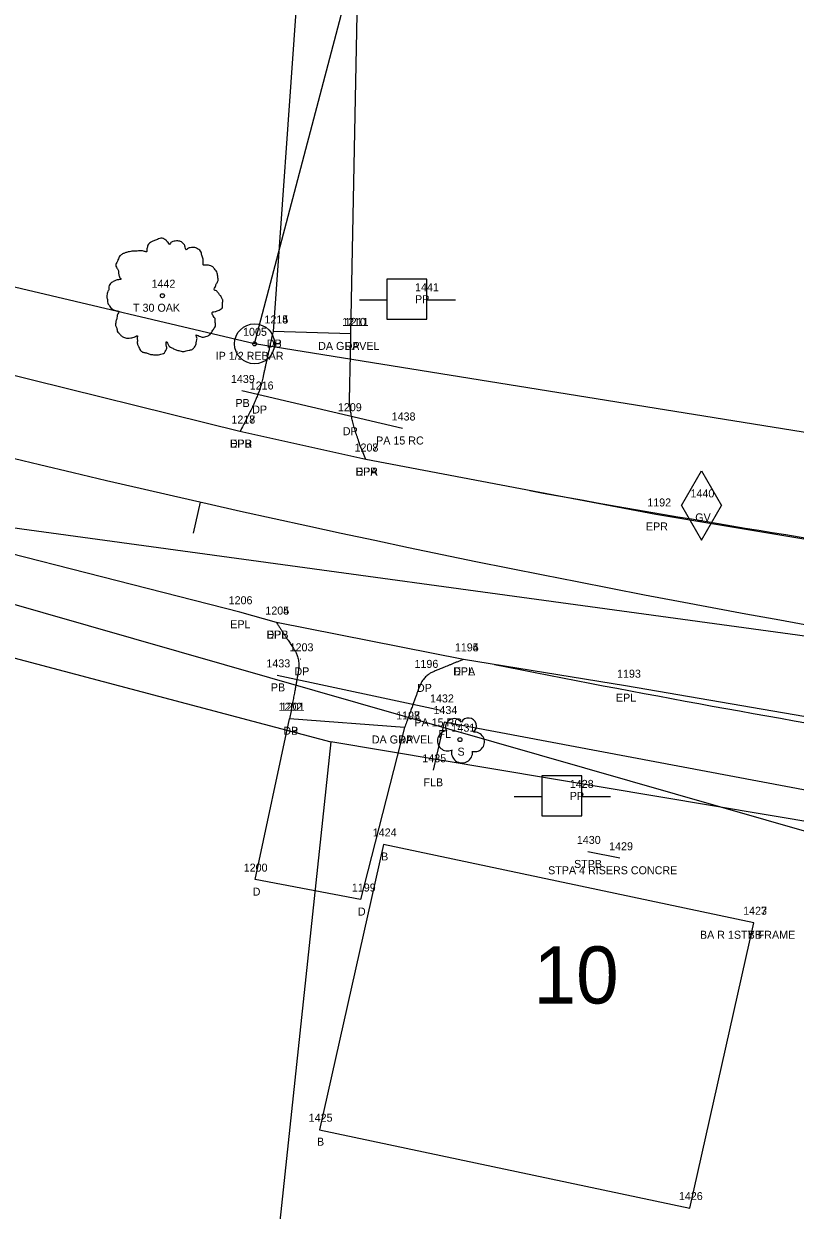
# Model space of a CAD drawing. Extents: x 1812113 to 1819860, y 1177395 to 1181185.
# Drawn here: x 1813371.7 to 1813468, y 1178709.1 to 1178857.4 of the extents above; entities that cross this region are included whole.
import ezdxf

# ---------------------------------------------------------------- set-up
doc = ezdxf.new("R2010")
doc.units = 0
for name, color, linetype in [('RD_EX_Bldg', 7, 'Continuous'), ('RD_EX_Bldg_txCode', 7, 'Continuous'), ('RD_EX_Conc', 7, 'Continuous'), ('RD_EX_Conc_txCode', 7, 'Continuous'), ('RD_EX_DR_Pipe', 7, 'Continuous'), ('RD_EX_DR_Pipe_txCode', 7, 'Continuous'), ('RD_EX_Driveway', 7, 'Continuous'), ('RD_EX_Driveway_txCode', 7, 'Continuous'), ('RD_EX_DV_Prop', 7, 'Continuous'), ('RD_EX_DV_Prop_txCode', 7, 'Continuous'), ('RD_EX_DV_PropPin', 7, 'Continuous'), ('RD_EX_DV_TX_Prop', 7, 'Continuous'), ('RD_EX_Fence_Other', 7, 'Continuous'), ('RD_EX_Fence_Other_txCode', 7, 'Continuous'), ('RD_EX_Road', 7, 'Continuous'), ('RD_EX_Road_txCode', 7, 'Continuous'), ('RD_EX_RW', 7, 'Continuous'), ('RD_EX_UT', 7, 'Continuous'), ('RD_EX_UT_txCode', 7, 'Continuous'), ('RD_EX_VEG', 7, 'Continuous'), ('RD_EX_VEG_txCode', 7, 'Continuous'), ('RD_HC_CL', 7, 'Continuous'), ('RD_HC_Data_Tic', 7, 'Continuous'), ('RD_PD_ALT1_TrvlWay', 7, 'Continuous'), ('RD_PD_PatLn1', 7, 'Continuous'), ('RD_SMD_Locator', 7, 'Continuous')]:
    doc.layers.add(name, color=color, linetype=linetype)

msp = doc.modelspace()

# ---------------------------------------------------------------- linework, layer by layer
at = {"layer": 'RD_EX_Bldg'}
msp.add_lwpolyline([(1813462.81, 1178745.04), (1813416.58, 1178754.82), (1813408.58, 1178719.18), (1813454.82, 1178709.39), (1813462.81, 1178745.04)], dxfattribs=at)
at = {"layer": 'RD_EX_Conc'}
msp.add_line((1813446.08, 1178753.1), (1813442.1, 1178753.89), dxfattribs=at)
at = {"layer": 'RD_EX_DR_Pipe'}
for p, q in [((1813418.94, 1178806.8), (1813398.87, 1178811.49)), ((1813423.73, 1178771.57), (1813403.29, 1178775.95))]:
    msp.add_line(p, q, dxfattribs=at)
at = {"layer": 'RD_EX_Driveway'}
for p, q in [((1813405.99, 1178863.99), (1813402.78, 1178818.92)), ((1813412.51, 1178818.62), (1813413.38, 1178863.09)), ((1813412.51, 1178818.62), (1813402.78, 1178818.92)), ((1813419.21, 1178769.44), (1813404.84, 1178770.53))]:
    msp.add_line(p, q, dxfattribs=at)
msp.add_lwpolyline([(1813419.21, 1178769.44), (1813413.68, 1178747.94), (1813400.54, 1178750.43), (1813404.84, 1178770.53)], dxfattribs=at)
for points in [[(1813402.78, 1178818.92), (1813401.87, 1178814.8), (1813400.96, 1178810.67), (1813398.64, 1178806.42)], [(1813414.35, 1178802.92), (1813412.27, 1178807.96), (1813412.39, 1178813.29), (1813412.51, 1178818.62)], [(1813403.21, 1178782.55), (1813404.72, 1178780.25), (1813406.23, 1178777.96), (1813405.54, 1178774.24), (1813404.84, 1178770.53)], [(1813426.54, 1178777.95), (1813424.03, 1178776.92), (1813421.53, 1178775.89), (1813420.37, 1178772.67), (1813419.21, 1178769.44)]]:
    msp.add_open_spline(points, degree=2, dxfattribs=at)
at = {"layer": 'RD_EX_DV_Prop'}
for p, q in [((1813400.47, 1178817.38), (1813428.23, 1178922.79)), ((1813400.47, 1178817.38), (1813327.69, 1178834.58)), ((1813275.15, 1178803.43), (1813409.98, 1178767.65)), ((1813409.98, 1178767.65), (1813396.08, 1178636.38))]:
    msp.add_line(p, q, dxfattribs=at)
at = {"layer": 'RD_EX_DV_PropPin'}
for radius in [2.5, 0.25]:
    msp.add_circle((1813400.47, 1178817.38), radius, dxfattribs=at)
at = {"layer": 'RD_EX_Fence_Other'}
msp.add_lwpolyline([(1813499.51, 1178755.92), (1813424.16, 1178770.12), (1813422.76, 1178764.09)], dxfattribs=at)
at = {"layer": 'RD_EX_Road'}
for p, q in [((1813398.64, 1178806.42), (1813355.44, 1178817.13)), ((1813414.35, 1178802.92), (1813398.64, 1178806.42)), ((1813450.56, 1178796.06), (1813414.35, 1178802.92)), ((1813499.47, 1178787.87), (1813450.56, 1178796.06))]:
    msp.add_line(p, q, dxfattribs=at)
msp.add_lwpolyline([(1813732.94, 1178707.95), (1813689.88, 1178731.75), (1813641.71, 1178744.36), (1813593.37, 1178752.09), (1813544.49, 1178758.77), (1813495.45, 1178766.29), (1813446.8, 1178774.66), (1813426.54, 1178777.95), (1813403.21, 1178782.55), (1813398.65, 1178783.84), (1813350.68, 1178796.09), (1813343.23, 1178797.92), (1813318.7, 1178804.23), (1813303.26, 1178808.85), (1813256.8, 1178823.17), (1813209.81, 1178838.91), (1813163.27, 1178855.57)], dxfattribs=at)
at = {"layer": 'RD_EX_RW'}
for p, q in [((1813632.03, 1178780.07), (1813400.47, 1178817.38)), ((1813539.17, 1178745.92), (1813409.98, 1178767.65))]:
    msp.add_line(p, q, dxfattribs=at)
at = {"layer": 'RD_EX_UT'}
for p, q in [((1813422, 1178825.46), (1813417, 1178825.46)), ((1813417, 1178825.46), (1813417, 1178820.46)), ((1813422, 1178820.46), (1813422, 1178825.46)), ((1813413.57, 1178822.89), (1813417.04, 1178822.89)), ((1813421.93, 1178822.89), (1813425.57, 1178822.89)), ((1813417, 1178820.46), (1813422, 1178820.46)), ((1813453.78, 1178797.19), (1813456.28, 1178801.52)), ((1813456.28, 1178801.52), (1813458.78, 1178797.19)), ((1813453.78, 1178797.19), (1813456.28, 1178792.86)), ((1813456.28, 1178792.86), (1813458.78, 1178797.19)), ((1813441.32, 1178763.4), (1813436.32, 1178763.4)), ((1813436.32, 1178763.4), (1813436.32, 1178758.4)), ((1813441.32, 1178758.4), (1813441.32, 1178763.4)), ((1813432.89, 1178760.83), (1813436.36, 1178760.83)), ((1813441.25, 1178760.83), (1813444.89, 1178760.83)), ((1813436.32, 1178758.4), (1813441.32, 1178758.4))]:
    msp.add_line(p, q, dxfattribs=at)
msp.add_lwpolyline([(1812996.89, 1178919.95), (1813204.49, 1178832.44), (1813481.3, 1178753.03), (1813490.2, 1178706.76)], dxfattribs=at)
at = {"layer": 'RD_EX_VEG'}
for centre, radius in [((1813388.96, 1178823.39), 0.25), ((1813388.95, 1178823.37), 0.0001), ((1813426.12, 1178767.92), 0.25)]:
    msp.add_circle(centre, radius, dxfattribs=at)
for centre, radius, start, end in [((1813427.17, 1178769.63), 0.995, 308.7626, 152.0467), ((1813425.4, 1178769.47), 1.08, 34.9763, 204.756), ((1813424.56, 1178767.77), 1.26, 96.4518, 294.734), ((1813427.96, 1178767.64), 1.22, 256.5667, 98.1046), ((1813426.37, 1178766.33), 1.32, 166.8827, 5.7589)]:
    msp.add_arc(centre, radius, start, end, dxfattribs=at)
for points in [[(1813389.09, 1178830.56), (1813388.79, 1178830.58), (1813388.47, 1178830.48), (1813388.22, 1178830.38), (1813387.99, 1178830.31), (1813387.77, 1178830.21), (1813387.47, 1178830.03), (1813387.24, 1178829.83), (1813387.12, 1178829.58), (1813387.07, 1178829.36), (1813387.02, 1178829.09), (1813387.02, 1178828.91), (1813386.89, 1178828.89), (1813386.74, 1178828.91), (1813386.49, 1178828.99), (1813386.24, 1178828.99), (1813385.99, 1178828.99), (1813385.64, 1178828.96), (1813385.29, 1178828.96), (1813385.02, 1178828.91), (1813384.69, 1178828.86), (1813384.32, 1178828.74), (1813383.97, 1178828.61), (1813383.67, 1178828.36), (1813383.42, 1178827.89), (1813383.29, 1178827.54), (1813383.14, 1178827.29), (1813383.29, 1178826.84), (1813383.47, 1178826.49), (1813383.49, 1178826.29), (1813383.57, 1178825.86), (1813383.67, 1178825.64), (1813383.79, 1178825.44), (1813383.72, 1178825.41), (1813383.34, 1178825.36), (1813383.04, 1178825.26), (1813382.62, 1178825.04), (1813382.39, 1178824.81), (1813382.29, 1178824.49), (1813382.27, 1178824.14), (1813382.17, 1178823.94), (1813382.09, 1178823.66), (1813382.07, 1178823.59), (1813382.02, 1178823.26), (1813382.12, 1178822.81), (1813382.14, 1178822.46), (1813382.27, 1178822.24), (1813382.42, 1178822.06), (1813382.59, 1178821.81), (1813382.99, 1178821.59), (1813383.32, 1178821.49), (1813383.52, 1178821.46), (1813383.34, 1178820.96), (1813383.29, 1178820.61), (1813383.17, 1178820.21), (1813383.17, 1178820.14), (1813383.12, 1178819.66), (1813383.27, 1178819.34), (1813383.34, 1178818.96), (1813383.52, 1178818.74), (1813383.79, 1178818.44), (1813384.12, 1178818.21), (1813384.62, 1178818.09), (1813385.02, 1178818.11), (1813385.59, 1178818.29), (1813385.84, 1178818.36), (1813385.82, 1178818.19), (1813385.84, 1178817.81), (1813385.84, 1178817.39), (1813385.99, 1178817.07), (1813386.09, 1178816.79), (1813386.24, 1178816.54), (1813386.57, 1178816.32), (1813386.97, 1178816.24), (1813387.39, 1178816.09), (1813387.84, 1178816.02), (1813388.34, 1178815.99), (1813388.94, 1178816.14), (1813389.22, 1178816.27), (1813389.32, 1178816.44), (1813389.52, 1178816.82), (1813389.47, 1178817.04), (1813389.49, 1178817.64), (1813389.59, 1178817.47), (1813389.77, 1178817.12), (1813390.27, 1178816.82), (1813390.67, 1178816.64), (1813391.14, 1178816.49), (1813391.44, 1178816.42), (1813391.92, 1178816.49), (1813392.29, 1178816.57), (1813392.67, 1178816.69), (1813392.97, 1178816.97), (1813393.14, 1178817.24), (1813393.19, 1178817.52), (1813393.26, 1178817.89), (1813393.31, 1178818.06)], [(1813393.31, 1178818.06), (1813393.24, 1178818.24), (1813393.19, 1178818.49), (1813393.26, 1178818.46), (1813393.44, 1178818.41), (1813393.71, 1178818.29), (1813393.94, 1178818.21), (1813394.26, 1178818.24), (1813394.54, 1178818.34), (1813394.99, 1178818.61), (1813395.26, 1178819.09), (1813395.54, 1178819.49), (1813395.61, 1178819.81), (1813395.56, 1178820.04), (1813395.54, 1178820.54), (1813395.34, 1178820.79), (1813395.29, 1178820.91), (1813395.19, 1178821.31), (1813395.26, 1178821.36), (1813395.54, 1178821.41), (1813395.91, 1178821.54), (1813396.19, 1178821.66), (1813396.41, 1178821.84), (1813396.49, 1178822.06), (1813396.46, 1178822.46), (1813396.51, 1178822.86), (1813396.44, 1178823.01), (1813396.34, 1178823.16), (1813396.26, 1178823.36), (1813396.11, 1178823.51), (1813396.01, 1178823.66), (1813395.91, 1178823.76), (1813395.79, 1178823.91), (1813395.61, 1178824.04), (1813395.46, 1178824.09), (1813395.41, 1178824.24), (1813395.56, 1178824.44), (1813395.61, 1178824.54), (1813395.64, 1178824.76), (1813395.86, 1178825.11), (1813395.91, 1178825.51), (1813395.86, 1178825.94), (1813395.81, 1178826.21), (1813395.66, 1178826.49), (1813395.46, 1178826.74), (1813395.34, 1178826.91), (1813395.16, 1178827.04), (1813394.84, 1178827.16), (1813394.59, 1178827.21), (1813394.24, 1178827.21), (1813394.04, 1178827.26), (1813394.06, 1178827.31), (1813394.06, 1178827.46), (1813394.06, 1178827.74), (1813393.99, 1178828.19), (1813393.84, 1178828.69), (1813393.84, 1178828.71), (1813393.74, 1178828.96), (1813393.51, 1178829.16), (1813393.34, 1178829.26), (1813393.14, 1178829.38), (1813392.89, 1178829.41), (1813392.59, 1178829.41), (1813392.32, 1178829.36), (1813392.12, 1178829.26), (1813391.94, 1178829.13), (1813391.87, 1178829.28), (1813391.77, 1178829.58), (1813391.72, 1178829.73), (1813391.57, 1178829.91), (1813391.34, 1178830.11), (1813390.89, 1178830.23), (1813390.27, 1178830.16), (1813389.97, 1178829.96), (1813389.82, 1178829.78), (1813389.77, 1178829.91), (1813389.57, 1178830.11), (1813389.47, 1178830.28), (1813389.29, 1178830.41), (1813389.14, 1178830.51), (1813389.04, 1178830.56)]]:
    msp.add_spline(points, degree=3, dxfattribs=at)
at = {"layer": 'RD_HC_CL'}
msp.add_arc((1813766.93, 1180445.18), 1689.31, 243.58271, 262.2191, dxfattribs=at)
at = {"layer": 'RD_HC_Data_Tic'}
msp.add_line((1813393.7, 1178797.61), (1813392.81, 1178793.71), dxfattribs=at)
at = {"layer": 'RD_PD_ALT1_TrvlWay'}
for centre, radius, start, end in [((1813743.74, 1180497.85), 1726.67, 259.69377, 263.32028), ((1813772.51, 1180493.14), 1749.59, 258.72477, 262.35128)]:
    msp.add_arc(centre, radius, start, end, dxfattribs=at)
at = {"layer": 'RD_PD_PatLn1'}
msp.add_line((1813616.11, 1178760.78), (1813027.99, 1178841.14), dxfattribs=at)
at = {"layer": 'RD_SMD_Locator'}
for centre in [(1813402.78, 1178818.92), (1813402.78, 1178818.92), (1813412.51, 1178818.62), (1813412.51, 1178818.62), (1813398.87, 1178811.49), (1813400.96, 1178810.67), (1813412.27, 1178807.96), (1813398.64, 1178806.42), (1813398.64, 1178806.42), (1813418.94, 1178806.8), (1813414.35, 1178802.92), (1813414.35, 1178802.92), (1813450.56, 1178796.06), (1813398.65, 1178783.84), (1813403.21, 1178782.55), (1813403.21, 1178782.55), (1813406.23, 1178777.96), (1813426.54, 1178777.95), (1813426.54, 1178777.95), (1813403.29, 1178775.95), (1813421.53, 1178775.89), (1813446.8, 1178774.66), (1813423.73, 1178771.57), (1813404.84, 1178770.53), (1813404.84, 1178770.53), (1813419.21, 1178769.44), (1813419.21, 1178769.44), (1813424.16, 1178770.12), (1813422.76, 1178764.09), (1813416.58, 1178754.82), (1813442.1, 1178753.89), (1813446.08, 1178753.1), (1813400.54, 1178750.43), (1813413.68, 1178747.94), (1813462.81, 1178745.04), (1813462.81, 1178745.04), (1813408.58, 1178719.18), (1813454.82, 1178709.39)]:
    msp.add_circle(centre, 0.001, dxfattribs=at)

# ---------------------------------------------------------------- texts
at = {"layer": 'RD_EX_Bldg_txCode'}
for s, p in [('1424', (1813415.23, 1178755.82)), ('B', (1813416.27, 1178752.82)), ('1423', (1813461.47, 1178746.04)), ('1427', (1813461.47, 1178746.04)), ('BA R 1STY FRAME', (1813456.08, 1178743.04)), ('BB', (1813462.03, 1178743.04)), ('1425', (1813407.23, 1178720.18)), ('B', (1813408.27, 1178717.18)), ('1426', (1813453.45, 1178710.39))]:
    msp.add_text(s, height=1, dxfattribs=at).set_placement(p)
at = {"layer": 'RD_EX_Conc_txCode'}
for s, p in [('1430', (1813440.71, 1178754.89)), ('1429', (1813444.74, 1178754.1)), ('STPB', (1813440.36, 1178751.89)), ('STPA 4 RISERS CONCRE', (1813437.12, 1178751.1))]:
    msp.add_text(s, height=1, dxfattribs=at).set_placement(p)
at = {"layer": 'RD_EX_DR_Pipe_txCode'}
for s, p in [('1439', (1813397.52, 1178812.49)), ('PB', (1813398.09, 1178809.49)), ('1438', (1813417.59, 1178807.8)), ('PA 15 RC', (1813415.65, 1178804.8)), ('1433', (1813401.95, 1178776.95)), ('PB', (1813402.51, 1178773.95)), ('1432', (1813422.38, 1178772.57)), ('PA 15 RC', (1813420.43, 1178769.57))]:
    msp.add_text(s, height=1, dxfattribs=at).set_placement(p)
at = {"layer": 'RD_EX_Driveway_txCode'}
for s, p in [('1214', (1813401.71, 1178819.92)), ('1215', (1813401.71, 1178819.92)), ('1210', (1813411.41, 1178819.62)), ('1211', (1813411.73, 1178819.62)), ('DB', (1813402, 1178816.92)), ('DP', (1813402, 1178816.92)), ('DA GRAVEL', (1813408.41, 1178816.62)), ('DP', (1813411.73, 1178816.62)), ('1216', (1813399.87, 1178811.67)), ('DP', (1813400.18, 1178808.67)), ('1209', (1813410.88, 1178808.96)), ('1217', (1813397.58, 1178807.42)), ('DP', (1813411.49, 1178805.96)), ('DPB', (1813397.39, 1178804.42)), ('1208', (1813412.96, 1178803.92)), ('DPA', (1813413.08, 1178800.92)), ('1204', (1813401.82, 1178783.55)), ('DPB', (1813401.96, 1178780.55)), ('1203', (1813404.85, 1178778.96)), ('1195', (1813425.48, 1178778.95)), ('DP', (1813405.45, 1178775.96)), ('1196', (1813420.44, 1178776.89)), ('DPA', (1813425.27, 1178775.95)), ('DP', (1813420.75, 1178773.89)), ('1202', (1813403.46, 1178771.53)), ('1201', (1813403.74, 1178771.53)), ('1197', (1813418.15, 1178770.44)), ('1198', (1813418.15, 1178770.44)), ('DB', (1813404.06, 1178768.53)), ('DP', (1813404.06, 1178768.53)), ('DA GRAVEL', (1813415.11, 1178767.44)), ('DP', (1813418.43, 1178767.44)), ('1200', (1813399.12, 1178751.43)), ('1199', (1813412.62, 1178748.94)), ('D', (1813400.24, 1178748.43)), ('D', (1813413.37, 1178745.94))]:
    msp.add_text(s, height=1, dxfattribs=at).set_placement(p)
at = {"layer": 'RD_EX_DV_Prop_txCode'}
for s, p in [('1005', (1813399.04, 1178818.38)), ('IP 1/2 REBAR', (1813395.62, 1178815.38))]:
    msp.add_text(s, height=1, dxfattribs=at).set_placement(p)
at = {"layer": 'RD_EX_DV_TX_Prop'}
msp.add_text('10', height=7.14, dxfattribs=at).set_placement((1813435.31, 1178734.95))
at = {"layer": 'RD_EX_Fence_Other_txCode'}
for s, p in [('1434', (1813422.81, 1178771.12)), ('FL', (1813423.43, 1178768.12)), ('1435', (1813421.42, 1178765.09)), ('FLB', (1813421.56, 1178762.09))]:
    msp.add_text(s, height=1, dxfattribs=at).set_placement(p)
at = {"layer": 'RD_EX_Road_txCode'}
for s, p in [('1218', (1813397.58, 1178807.42)), ('EPR', (1813397.42, 1178804.42)), ('1207', (1813412.96, 1178803.92)), ('EPR', (1813413.12, 1178800.92)), ('1192', (1813449.5, 1178797.06)), ('EPR', (1813449.33, 1178794.06)), ('1206', (1813397.24, 1178784.84)), ('1205', (1813401.82, 1178783.55)), ('EPL', (1813397.44, 1178781.84)), ('EPL', (1813402, 1178780.55)), ('1194', (1813425.48, 1178778.95)), ('EPL', (1813425.34, 1178775.95)), ('1193', (1813445.73, 1178775.66)), ('EPL', (1813445.59, 1178772.66))]:
    msp.add_text(s, height=1, dxfattribs=at).set_placement(p)
at = {"layer": 'RD_EX_UT_txCode'}
for s, p in [('1441', (1813420.51, 1178823.95)), ('PP', (1813420.51, 1178822.45)), ('1440', (1813454.9, 1178798.19)), ('GV', (1813455.49, 1178795.19)), ('1428', (1813439.83, 1178761.89)), ('PP', (1813439.83, 1178760.39))]:
    msp.add_text(s, height=1, dxfattribs=at).set_placement(p)
at = {"layer": 'RD_EX_VEG_txCode'}
for s, p in [('1442', (1813387.61, 1178824.39)), ('T 30 OAK', (1813385.3, 1178821.39)), ('1431', (1813425.06, 1178768.92)), ('S', (1813425.81, 1178765.92))]:
    msp.add_text(s, height=1, dxfattribs=at).set_placement(p)

doc.saveas('drawing.dxf')
